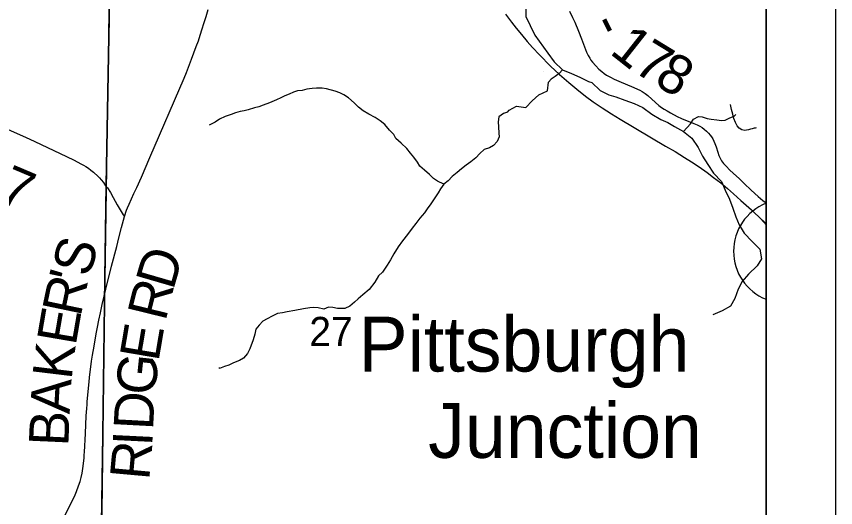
# Model space of a CAD drawing. Extents: x 0 to 34, y 0 to 22.
# Drawn here: x 16.323 to 17.5, y 15.132 to 15.839 of the extents above; entities that cross this region are included whole.
import ezdxf

# ---------------------------------------------------------------- set-up
doc = ezdxf.new("R2010")
doc.units = 0
for name, color, linetype in [('GM_X_City_Street', 7, 'Continuous'), ('GM_X_Corporation', 7, 'Continuous'), ('GM_X_County_Road', 7, 'Continuous'), ('GM_X_County_Road_Text', 7, 'Continuous'), ('GM_X_Major_River', 7, 'Continuous'), ('GM_X_Minor_River', 7, 'Continuous'), ('GM_X_Rail_Line', 7, 'Continuous'), ('GM_X_Section_Text', 7, 'Continuous'), ('GM_X_Township_Road', 7, 'Continuous'), ('GM_X_Township_Road_Text', 7, 'Continuous'), ('GM_X_Unincorporated_Text', 7, 'Continuous'), ('SH_Data', 7, 'Continuous')]:
    doc.layers.add(name, color=color, linetype=linetype)

msp = doc.modelspace()

# ---------------------------------------------------------------- linework, layer by layer
at = {"layer": 'GM_X_City_Street'}
msp.add_line((17.4, 15.4318), (17.4, 15.5699), dxfattribs=at)
msp.add_arc((17.4277, 15.5008), 0.0744, 111.8743, 248.1257, dxfattribs=at)
at = {"layer": 'GM_X_Corporation'}
msp.add_lwpolyline([(16.4419, 14.8642), (16.4498, 15.4626), (16.4516, 15.5964), (16.4611, 16.1288), (16.4603, 16.2617), (16.4689, 16.9245), (16.4703, 17.0036), (16.4704, 17.0104), (16.4807, 17.4161), (15.8844, 17.4269), (15.8426, 17.4278), (14.7561, 17.4645), (14.726, 17.4654), (14.0954, 17.4811), (13.2742, 17.4966)], dxfattribs=at)
for points in [[(16.4214, 13.6), (17.4, 13.6), (17.4, 16.913), (16.5516, 16.9243), (16.4689, 16.9245), (16.4603, 16.2617), (16.4611, 16.1288), (16.4516, 15.5964), (16.4498, 15.4626), (16.4419, 14.8642), (16.438, 14.5908), (16.4339, 14.3806), (16.4212, 13.6609)], [(15.4691, 15.9163), (16.4563, 15.9084), (16.441, 14.8856), (15.4475, 14.9085)], [(17.4, 14.8906), (17.4, 15.8967), (16.4563, 15.9084), (16.441, 14.8856)]]:
    msp.add_lwpolyline(points, close=True, dxfattribs=at)
at = {"layer": 'GM_X_County_Road'}
for points in [[(16.478, 15.551), (16.4809, 15.5597), (16.4822, 15.5631), (16.4846, 15.5684), (16.4882, 15.5763), (16.4916, 15.5838), (16.4955, 15.5924), (16.5022, 15.6073), (16.5143, 15.6356), (16.5636, 15.7496), (16.5669, 15.7577), (16.5745, 15.7773), (16.581, 15.7951), (16.5842, 15.8035), (16.5869, 15.8117), (16.5897, 15.8206), (16.5921, 15.8283), (16.5952, 15.8383), (16.598, 15.8484)], [(16.302, 15.68), (16.3356, 15.665), (16.3491, 15.6587), (16.3948, 15.6371), (16.4056, 15.6318), (16.4152, 15.6268), (16.4189, 15.6247), (16.4226, 15.6225), (16.4263, 15.6201), (16.4298, 15.6175), (16.4334, 15.6146), (16.4401, 15.6084), (16.4421, 15.6062), (16.4445, 15.6036), (16.4477, 15.5996), (16.4509, 15.5951), (16.4534, 15.592)], [(16.4534, 15.592), (16.4579, 15.5852), (16.4618, 15.5782), (16.4673, 15.5678), (16.476, 15.5533), (16.478, 15.551)], [(16.4512, 15.4465), (16.4595, 15.4793), (16.4668, 15.5077), (16.4699, 15.5203), (16.4737, 15.5349), (16.478, 15.551)], [(16.3902, 15.1169), (16.4059, 15.148), (16.409, 15.1552), (16.412, 15.1634), (16.4141, 15.1697), (16.4157, 15.1756), (16.417, 15.1818), (16.4181, 15.1886), (16.419, 15.1956), (16.4198, 15.2037), (16.4202, 15.2079), (16.4205, 15.2117), (16.4217, 15.2388), (16.4231, 15.2642), (16.4237, 15.2748), (16.4241, 15.2803), (16.4244, 15.2849), (16.427, 15.3132), (16.4276, 15.3194), (16.4307, 15.3426), (16.4321, 15.3514), (16.4343, 15.3645), (16.4374, 15.3821), (16.4392, 15.3917), (16.4412, 15.4018), (16.4434, 15.4125), (16.446, 15.4244), (16.4487, 15.4363), (16.4512, 15.4465)]]:
    msp.add_lwpolyline(points, dxfattribs=at)
at = {"layer": 'GM_X_Major_River'}
for points in [[(17.0549, 15.85), (17.0547, 15.8382), (17.061, 15.8254), (17.0676, 15.8118), (17.0862, 15.7855), (17.0954, 15.7731), (17.1073, 15.7619), (17.1203, 15.7564), (17.1322, 15.7512), (17.1448, 15.7449)], [(17.1448, 15.7449), (17.1497, 15.7435), (17.1616, 15.7319), (17.1742, 15.726), (17.1842, 15.7227), (17.1971, 15.7179), (17.2105, 15.7132), (17.2231, 15.7077), (17.2361, 15.698), (17.2487, 15.6905), (17.2587, 15.6861), (17.2686, 15.6802), (17.2812, 15.6731), (17.2935, 15.6634), (17.3024, 15.6499), (17.3086, 15.6378), (17.3164, 15.6258), (17.3245, 15.613), (17.3361, 15.601), (17.3412, 15.5885), (17.3474, 15.5757), (17.3521, 15.5629), (17.3565, 15.5504), (17.3612, 15.5387), (17.3685, 15.5267), (17.3801, 15.5147), (17.3912, 15.5038), (17.3937, 15.4898), (17.3874, 15.4798), (17.375, 15.4679), (17.3656, 15.4575), (17.3601, 15.4461), (17.3553, 15.4331), (17.349, 15.422), (17.337, 15.415), (17.3237, 15.4095)]]:
    msp.add_lwpolyline(points, dxfattribs=at)
at = {"layer": 'GM_X_Minor_River'}
for points in [[(17.0796, 15.7591), (17.0797, 15.7591)], [(17.1073, 15.7619), (17.1027, 15.7567), (17.0971, 15.7521), (17.0914, 15.7482), (17.0875, 15.7442)], [(17.0282, 15.7008), (17.031, 15.7039), (17.0416, 15.7094), (17.0549, 15.7077), (17.0639, 15.7173), (17.0736, 15.7257), (17.0861, 15.7316), (17.0875, 15.7442)], [(16.9371, 15.5974), (16.9279, 15.6014), (16.9222, 15.6055), (16.9164, 15.6111), (16.9091, 15.6174), (16.9022, 15.623), (16.899, 15.629), (16.894, 15.6361), (16.8889, 15.6421), (16.8839, 15.6485), (16.8754, 15.6563), (16.8681, 15.663), (16.865, 15.6687), (16.8588, 15.675), (16.8523, 15.6829), (16.8453, 15.6885), (16.8381, 15.6933), (16.8293, 15.6981), (16.8212, 15.7029), (16.8143, 15.7081), (16.8081, 15.7141), (16.8001, 15.7215), (16.7932, 15.726), (16.7874, 15.7289), (16.7806, 15.7311), (16.7684, 15.7343), (16.7619, 15.7353), (16.754, 15.7352), (16.7479, 15.7351), (16.74, 15.7338), (16.7332, 15.7322), (16.7267, 15.7313), (16.7207, 15.7297), (16.7147, 15.7269), (16.7083, 15.7245), (16.7027, 15.7214), (16.6966, 15.7186), (16.6865, 15.7143), (16.6771, 15.7107), (16.671, 15.7087), (16.665, 15.7071), (16.6556, 15.7042), (16.6499, 15.703), (16.6442, 15.7018), (16.6374, 15.7001), (16.6314, 15.6977), (16.6228, 15.6945), (16.6145, 15.691), (16.6081, 15.6867), (16.5995, 15.6824)], [(17.0282, 15.7008), (17.0225, 15.6991), (17.0158, 15.6941), (17.0152, 15.6868), (17.0153, 15.68), (17.0162, 15.6709), (17.0163, 15.6652), (17.0134, 15.6587), (17.0081, 15.6529), (17.0025, 15.6494), (16.995, 15.6474), (16.9886, 15.6416), (16.9827, 15.6354), (16.9759, 15.6296), (16.9688, 15.6245), (16.9625, 15.6194), (16.9561, 15.614), (16.949, 15.6082), (16.9431, 15.602), (16.9371, 15.5974), (16.9323, 15.5904), (16.9286, 15.5847), (16.9238, 15.5777), (16.9182, 15.5689), (16.913, 15.562), (16.909, 15.5562), (16.9026, 15.5485), (16.8967, 15.5408), (16.8915, 15.5339), (16.8848, 15.525), (16.8774, 15.5158), (16.8715, 15.5073), (16.8652, 15.4973), (16.8601, 15.4885), (16.8553, 15.4808), (16.8486, 15.4708), (16.843, 15.4654), (16.8379, 15.4566), (16.8297, 15.4458), (16.8207, 15.438), (16.814, 15.4326), (16.8084, 15.4276), (16.8017, 15.4217), (16.7945, 15.4186), (16.7843, 15.4184), (16.7775, 15.4198), (16.771, 15.4205), (16.7646, 15.4177), (16.7562, 15.4194), (16.7502, 15.4201), (16.7445, 15.4196), (16.735, 15.4179), (16.7226, 15.4158), (16.712, 15.4138), (16.7052, 15.4125), (16.698, 15.4112), (16.6901, 15.4077), (16.683, 15.4038), (16.6766, 15.4002), (16.6714, 15.3944), (16.6669, 15.3887), (16.6655, 15.3814), (16.663, 15.3734), (16.6579, 15.3604), (16.6546, 15.3539), (16.6491, 15.3469), (16.6434, 15.3438), (16.6348, 15.3402), (16.628, 15.3371), (16.6216, 15.3351), (16.6144, 15.3323), (16.6145, 15.3336)], [(17.2812, 15.6731), (17.2915, 15.684), (17.2959, 15.6909), (17.3027, 15.6944), (17.3084, 15.6941), (17.3156, 15.6916), (17.3213, 15.6906), (17.3293, 15.6896), (17.3358, 15.6889), (17.3414, 15.6894), (17.3478, 15.6929), (17.3542, 15.6953), (17.3568, 15.6976)], [(16.9371, 15.5974), (16.9384, 15.5986)]]:
    msp.add_lwpolyline(points, dxfattribs=at)
msp.add_spline([(17.3859, 15.6782), (17.3802, 15.677), (17.3695, 15.6747), (17.349, 15.7117)], degree=3, dxfattribs=at)
at = {"layer": 'GM_X_Rail_Line'}
msp.add_line((17.3942, 15.5454), (17.4, 15.5388), dxfattribs=at)
msp.add_lwpolyline([(17.0256, 15.8417), (17.0341, 15.8303), (17.041, 15.8216), (17.0485, 15.8124), (17.0569, 15.8026), (17.0645, 15.794), (17.0742, 15.7835), (17.0904, 15.7671), (17.1031, 15.7552), (17.1164, 15.7437), (17.1282, 15.7338), (17.1406, 15.7241), (17.1517, 15.7159), (17.1645, 15.7071), (17.1781, 15.6983), (17.1905, 15.6907), (17.2555, 15.6521), (17.2692, 15.6441), (17.2829, 15.6356), (17.2931, 15.6295), (17.3039, 15.6222), (17.3152, 15.6143), (17.3247, 15.6069), (17.3348, 15.5992), (17.3448, 15.5909), (17.3534, 15.5835), (17.3639, 15.5739), (17.3789, 15.5603), (17.3942, 15.5454), (17.4, 15.5409)], dxfattribs=at)
at = {"layer": 'GM_X_Township_Road'}
msp.add_lwpolyline([(17.1177, 15.8459), (17.122, 15.8368), (17.125, 15.8303), (17.1305, 15.8174), (17.1347, 15.8065), (17.1421, 15.7872), (17.1446, 15.7822), (17.1466, 15.7787), (17.1484, 15.7758), (17.1504, 15.7729), (17.1554, 15.7673), (17.1598, 15.7628), (17.1639, 15.7592), (17.1675, 15.7566), (17.1709, 15.7541), (17.1766, 15.751), (17.1818, 15.7484), (17.1884, 15.7452), (17.2099, 15.7364), (17.2152, 15.7341), (17.2186, 15.7325), (17.2221, 15.7305), (17.2265, 15.7277), (17.2302, 15.7247), (17.2409, 15.7149), (17.246, 15.7106), (17.2498, 15.7077), (17.2535, 15.7053), (17.258, 15.7026), (17.2626, 15.6999), (17.2725, 15.6946), (17.2784, 15.6919), (17.2964, 15.6846), (17.3012, 15.6826), (17.3048, 15.6809), (17.3081, 15.6789), (17.3113, 15.6765), (17.3146, 15.6736), (17.3173, 15.6707), (17.3197, 15.668), (17.3218, 15.6654), (17.3234, 15.6626), (17.3251, 15.6593), (17.3266, 15.6559), (17.3282, 15.6508), (17.3305, 15.6432), (17.3321, 15.6385), (17.334, 15.6346), (17.3361, 15.6311), (17.3391, 15.6269), (17.343, 15.6225), (17.3473, 15.6179), (17.3532, 15.6129), (17.3613, 15.6054), (17.3688, 15.5981), (17.3787, 15.5889), (17.3885, 15.5798), (17.3955, 15.5738), (17.4, 15.5705)], dxfattribs=at)
at = {"layer": 'SH_Data'}
for points in [[(10.5, 20.5), (17.5, 20.5), (17.5, 13.5), (10.5, 13.5)], [(10.6, 20.4), (17.4, 20.4), (17.4, 13.6), (10.6, 13.6)]]:
    msp.add_lwpolyline(points, close=True, dxfattribs=at)

# ---------------------------------------------------------------- texts
at = {"layer": 'GM_X_County_Road_Text'}
for s, height, rotation, p in [('C-17', 0.05682, 337.0495, (16.1812, 15.6217)), ('S', 0.0568, 73.7518, (16.4272, 15.4621)), ('D', 0.0568, 73.7669, (16.5478, 15.4436)), ("'", 0.0568, 75.7941, (16.4242, 15.4505)), ('R', 0.0568, 78.1718, (16.4148, 15.4054)), ('R', 0.0568, 76.1909, (16.5368, 15.3989)), ('E', 0.0568, 80.2594, (16.4077, 15.364)), ('E', 0.0568, 80.346, (16.5267, 15.3409)), ('K', 0.0568, 83.1203, (16.4018, 15.3151)), ('G', 0.0568, 83.9233, (16.5215, 15.2921)), ('A', 0.0568, 86.8072, (16.3991, 15.2662)), ('D', 0.0568, 86.9458, (16.5189, 15.243)), ('B', 0.0568, 87.4192, (16.3971, 15.2197)), ('I', 0.0568, 87.1556, (16.5177, 15.2197)), ('R', 0.0568, 84.8331, (16.5134, 15.1707))]:
    msp.add_text(s, height=height, rotation=rotation, dxfattribs=at).set_placement(p)
at = {"layer": 'GM_X_Section_Text'}
msp.add_text('27', height=0.04186, rotation=0, dxfattribs=at).set_placement((16.7436, 15.3646))
at = {"layer": 'GM_X_Township_Road_Text'}
for s, rotation, p in [('-', 296.8055, (17.1463, 15.8274)), ('1', 321.7427, (17.1737, 15.7861)), ('7', 328.5848, (17.207, 15.7604)), ('8', 328.9085, (17.237, 15.7421))]:
    msp.add_text(s, height=0.0568, rotation=rotation, dxfattribs=at).set_placement(p)
at = {"layer": 'GM_X_Unincorporated_Text'}
for s, p in [('Pittsburgh', (16.8144, 15.3278)), ('Junction', (16.9144, 15.2037))]:
    msp.add_text(s, height=0.07898, rotation=0, dxfattribs=at).set_placement(p)

doc.saveas('drawing.dxf')
